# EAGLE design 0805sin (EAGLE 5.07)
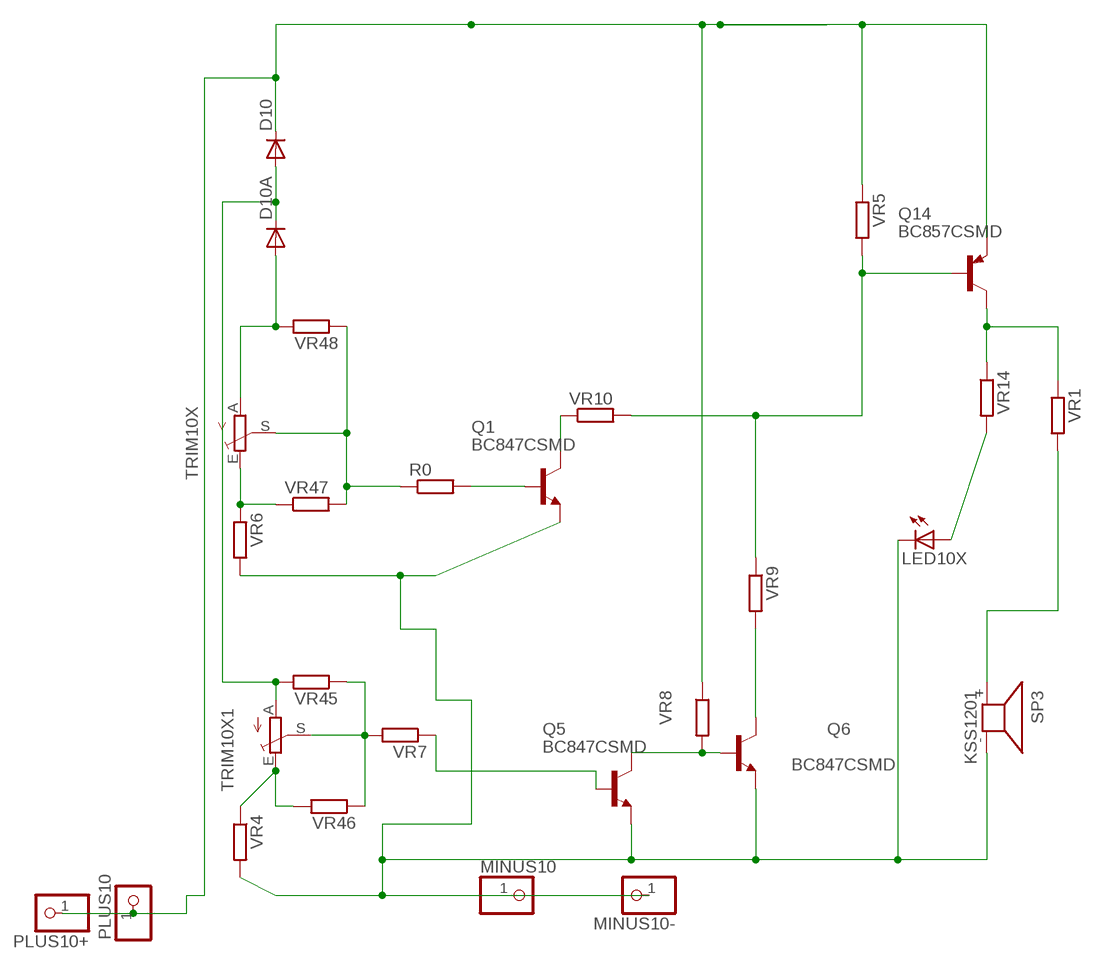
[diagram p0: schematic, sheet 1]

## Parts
D10  DIODE-MINIMELF  [MINIMELF]
D10A  DIODE-MINIMELF  [MINIMELF]
LED10X  LEDCHIPLED_1206  [CHIPLED_1206]
MINUS10  PINHD-1X14.5MM  [1X4MM5]
MINUS10-  PINHD-1X11X0.4  [1X01]
PLUS10  PINHD-1X14.5MM  [1X4MM5]
PLUS10+  PINHD-1X11X0.4  [1X01]
Q1  BC847CSMD  [SOT23]
Q5  BC847CSMD  [SOT23]
Q6  BC847CSMD  [SOT23]
Q14  BC857CSMD  [SOT23-BEC]
R0  R-EU_R0805  [R0805]
SP3  KSS1201  KSS12017MM  [KSS1202]
TRIM10X  TRIM_EU-S64W  [S64W]
TRIM10X1  TRIM_EU-S64W  [S64W]
VR1  R-EU_R0805  [R0805]
VR4  R-EU_R1206  [R1206]
VR5  R-EU_R0805  [R0805]
VR6  R-EU_R1206  [R1206]
VR7  R-EU_M1206  [M1206]
VR8  R-EU_R1206  [R1206]
VR9  R-EU_R0805  [R0805]
VR10  R-EU_R0805  [R0805]
VR14  R-EU_R0805  [R0805]
VR45  R-EU_R0805  [R0805]
VR46  R-EU_R0805  [R0805]
VR47  R-EU_R0805  [R0805]
VR48  R-EU_R0805  [R0805]

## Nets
B: R0.1 TRIM10X.S VR47.2 VR48.1
N$1: SP3.+ VR1.2
N$2: Q1.3(C) VR10.1
N$3: Q5.3(C) Q6.1(B) VR8.2
N$4: LED10X.A VR14.2
N$5: Q6.3(C) VR9.2
N$6: Q14.B VR5.2 VR9.1 VR10.2
N$7: Q1.1(B) R0.2
N$8: Q14.C VR1.1 VR14.1
N$14: D10A.A TRIM10X.A VR48.2
N$17: D10.A D10A.C TRIM10X1.A VR45.2
N$22: TRIM10X1.S VR7.2 VR45.1 VR46.1
N$24: TRIM10X1.E VR4.1 VR46.2
N$128: TRIM10X.E VR6.1 VR47.1
N$168: Q5.1(B) VR7.1
PLUS11: D10.C PLUS10+.1 PLUS10.1 Q14.E VR5.1 VR8.1
VSS: LED10X.C MINUS10-.1 MINUS10.1 Q1.2(E) Q5.2(E) Q6.2(E) SP3.- VR4.2 VR6.2

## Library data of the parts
D10 D10A = diode:DIODE-: DIODE
LED10X = led:LED: LED
MINUS10 MINUS10- PLUS10 PLUS10+ = pinhead:PINHD-1X1: PIN HEADER
Q1 Q5 Q6 = transistor-npn:BC847*: NPN Transistor
Q14 = transistor-pnp:BC857*: PNP Transistror
R0 VR1 VR4-VR10 VR14 VR45-VR48 = rcl-2:R-EU_: RESISTOR, European symbol
SP3 = buzzer:KSS1201: SPEAKER
TRIM10X TRIM10X1 = pot:TRIM_EU-: POTENTIOMETER

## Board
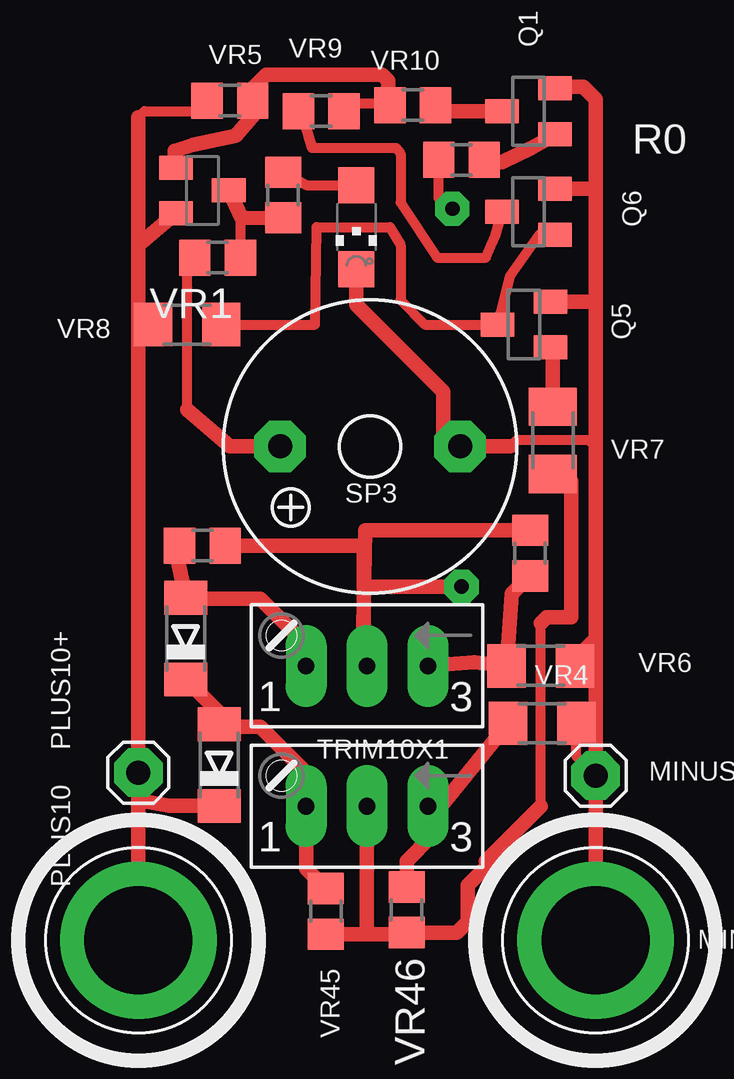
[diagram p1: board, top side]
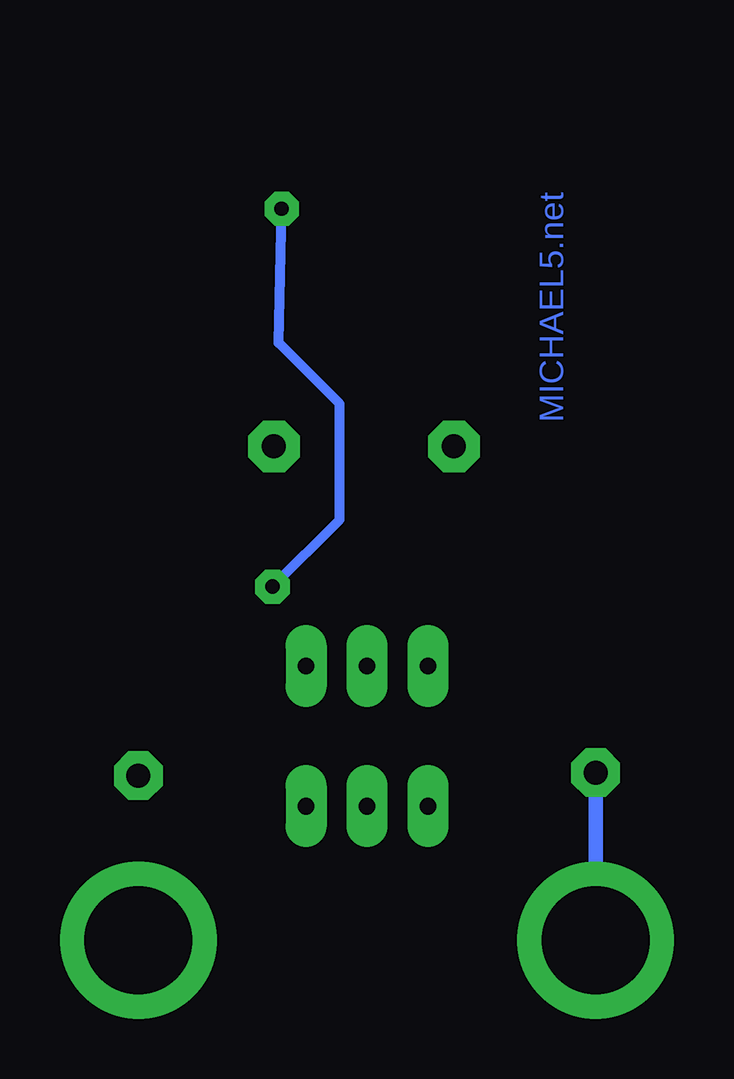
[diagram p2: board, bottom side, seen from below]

No outline drawn. Coordinates in mm, seen from the top.
Copper layers (1*16): Top 0.035mm / dielectric 1.5mm / Bottom 0.035mm
Design rules "default *": minimum track width 8mil, minimum drill 4mil, track to track 8mil, track to pad 8mil, pad to pad 8mil, via to via 8mil, smd to smd 8mil, copper to edge 40mil, drill to drill 8mil, minimum pad ring 20mil, minimum via ring 8mil, stop-mask expansion 4mil, vias tented up to drill 0mil, thermal gap 10mil

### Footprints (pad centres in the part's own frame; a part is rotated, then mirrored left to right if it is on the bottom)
MINIMELF = smd 1.4 x 1.8: A 1.7,0; C -1.7,0
CHIPLED_1206 = smd 1.5 x 1.5: A 0,-1.75; C 0,1.75
1X4MM5 = drill 4.5 pad 6.35 round: 1 0,0
1X01 = drill 1 pad 1.676 octagon: 1 0,0
SOT23 = smd 1 x 1.4: 1 -0.95,-1.1; 2 0.95,-1.1; 3 0,1.1
SOT23-BEC = smd 1 x 1.4: B -0.95,-1.1; C 0,1.1; E 0.95,-1.1
R0805 = smd 1.3 x 1.5: 1 -0.95,0; 2 0.95,0
KSS1202 = drill 1 pad 2.159 octagon: + 3.75,0; - -3.75,0
S64W = drill 0.7 long: A 2.54,1.27; E -2.54,1.27; S 0,1.27
R1206 = smd 1.6 x 1.803: 1 -1.422,0; 2 1.422,0
M1206 = smd 1.6 x 2: 1 -1.4,0; 2 1.4,0

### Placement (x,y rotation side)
D10  74.49,16.19 90 top
D10A  73.09,21.46 90 top
LED10X  80.2,38.61 180 top
MINUS10  90.17,8.89 0 top
MINUS10-  90.17,15.75 0 top
PLUS10  71.12,8.89 0 top
PLUS10+  71.12,15.88 0 top
Q1  87.38,43.43 90 top
Q5  87.19,34.54 90 top
Q6  87.38,39.24 90 top
Q14  73.79,40.13 270 top
R0  84.58,41.4 0 top
SP3  80.77,29.46 180 top
TRIM10X  80.64,21.59 180 top
TRIM10X1  80.64,15.75 180 top
VR1  74.42,37.34 180 top
VR4  87.95,17.93 0 top
VR5  74.93,43.88 0 top
VR6  87.88,20.32 0 top
VR7  88.39,29.72 270 top
VR8  73.15,34.54 0 top
VR9  78.74,43.43 180 top
VR10  82.55,43.69 180 top
VR14  77.15,39.94 90 top
VR45  78.93,10.1 90 top
VR46  82.3,10.16 90 top
VR47  87.44,25.02 90 top
VR48  73.79,25.34 180 top

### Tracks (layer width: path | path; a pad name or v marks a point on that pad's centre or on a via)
B  (via drill 0.6 pad 1.42)
  Top 0.406: R0.1 83.63,39.81 v84.2,39.37 | 80.48,21.96 80.62,23.62
  Top 0.61: VR47.2 80.58,25.97 80.48,21.96 80.77,20.83 80.77,20.45 TRIM10X.S 80.52,20.45 80.52,25.34 VR48.1 | 80.62,23.62 v84.58,23.62
  Bottom 0.406: v84.2,39.37 84.33,33.78 81.79,31.24 81.79,26.42 v84.58,23.62
N$1
  Top 0.406: 73.15,30.99 73.15,37.02 VR1.2
  Top 0.61: SP3.+ 74.93,29.46 73.15,30.99
N$2
  Top 0.406: VR10.1 83.75,43.43
  Top 0.61: 83.75,43.43 Q1.3
N$3
  Top 0.406: VR8.2 78.49,34.54 78.55,38.61 81.6,38.61 82.04,37.85 82.04,35.56 83.06,34.54 Q5.3 86.11,34.56 86.61,36.58 87.82,38.29 Q6.1
N$4
  Top 0.406: LED10X.A 78.11,40.36 VR14.2
N$5
  Top 0.406: Q6.3 85.98,38.23 85.6,37.34 83.57,37.34 82.04,39.62 82.04,41.66 81.85,41.91 78.36,41.91 77.98,43.25 VR9.2
N$6
  Top 0.406: VR10.2 81.53,43.75 80.01,43.75 VR9.1 | 75.95,43.3 VR5.2
  Top 0.61: VR5.2 75.88,44.38 76.45,44.96 81.28,44.96 81.53,44.7 81.53,43.75 | Q14.B 72.69,40.94 72.64,41.78 73.41,42.04 75.18,42.42 75.95,43.3
N$7
  Top 0.406: R0.2 86.26,41.3 | 88.41,42.42 Q1.1
  Top 0.61: 86.26,41.3 87.5,41.91 88.41,42.42
N$8
  Top 0.406: 75.42,38.96 75.37,38.96 VR1.1
  Top 0.61: VR14.1 75.42,38.96 Q14.C
N$14
  Top 0.61: TRIM10X.A 78.11,21.21 76.2,23.11 72.59,23.11 D10A.A 72.77,24.64 VR48.2
N$17
  Top 0.61: D10.A 74.69,17.89 | D10.A 74.6,17.78 76.2,17.78 78.11,15.88 TRIM10X1.A 78.11,11.87 VR45.2 | D10.A 74.49,18.37 D10A.C
N$22
  Top 0.406: 85.6,11.94 85.6,12.19 | 87.88,14.48 87.88,22.1 | 89.15,28.01 88.7,28.01 VR7.2 | 80.77,9.14 80.64,9.27 | VR45.1 | 82.23,9.14 VR46.1
  Top 0.61: VR46.1 84.39,9.21 84.84,9.65 84.84,11.18 85.6,11.94 | 85.6,12.19 87.88,14.48 | 87.88,22.1 88.14,22.35 89.15,22.35 89.15,28.01 | 80.64,9.27 TRIM10X1.S | VR45.1 80.77,9.14 82.23,9.14
N$24
  Top 0.406: 83.31,13.21 83.31,14.35 TRIM10X1.E
  Top 0.61: VR4.1 83.86,14.64 TRIM10X1.E | VR46.2 82.3,12.19 83.31,13.21
N$128
  Top 0.61: VR47.1 86.67,23.33 VR6.1 85.11,20.47 TRIM10X.E
N$168
  Top 0.406: 88.39,33.49 Q5.1
  Top 0.61: VR7.1 88.39,33.49
PLUS11
  Top 0.406: VR8.1 71.73,33.93 71.12,34.54 | 71.12,43.18 71.37,43.43 73.92,43.43 VR5.1 | 71.12,36.58 71.12,37.85
  Top 0.61: 72.5,14.49 D10.C 72.4,14.49 71.12,14.73 | PLUS10.1 71.12,14.73 | 71.12,14.73 PLUS10+.1 71.12,34.54 71.12,36.58 71.12,43.18 | 71.12,37.85 Q14.E
  Bottom 0.61: PLUS10.1 PLUS10+.1
VSS
  Top 0.406: VR6.2 89.31,20.73 90.17,21.59 | 88.54,44.45 Q1.2 | 86.61,29.46 86.87,29.72 89.92,29.72 90.17,29.46 | 90.17,35.56 90.1,35.49 | 90.17,40.13 90.11,40.19 | SP3.- 83.82,29.82 | VR4.2 89.37,16.55 MINUS10-.1
  Top 0.61: MINUS10.1 MINUS10-.1 90.17,21.59 90.17,29.46 90.17,35.56 90.17,40.13 90.17,43.94 89.66,44.45 88.54,44.45 | 86.61,29.46 SP3.- | 90.1,35.49 Q5.2 | 90.11,40.19 Q6.2 | LED10X.C 80.2,35.37 83.82,31.75 83.82,29.82

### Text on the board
Bottom: MICHAEL5.net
